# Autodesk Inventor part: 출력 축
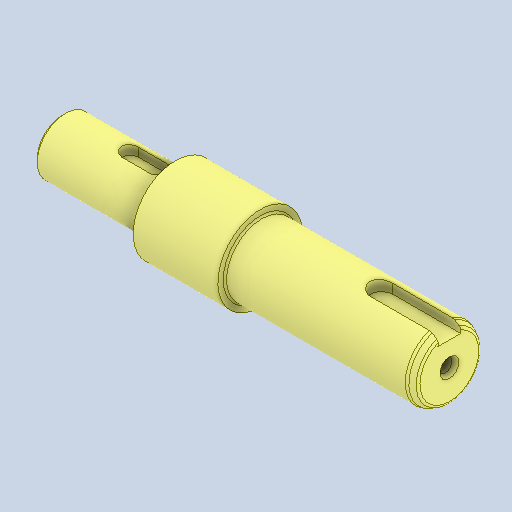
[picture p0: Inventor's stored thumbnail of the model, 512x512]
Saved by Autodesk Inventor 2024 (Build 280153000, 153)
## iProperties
Created: 2025-11
Part Number: 출력 축
Material: 강철, 탄소
Document SubType Name: Modeling
Designer: Edu07
Density: 7.85 g/cm^3
Appearance: 기본값
Author: jhkim
Sending System: Autodesk Inventor 2026
Preprocessor: ST-DEVELOPER v20.1
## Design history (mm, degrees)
node "출력 축1"
node "솔리드2"
node "솔리드1"
